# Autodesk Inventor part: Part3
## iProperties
Shininess: 64.0
Length Units: 11269
Angle Units: 11279
Time Units: 11290
Mass Units: 11283
Length Display Precision: 3
Angle Display Precision: 2
Compacted: True
Created: 2002-07
Part Number: Part3
Document SubType Name: Modeling
Designer: Administrator
Density: 0.0
Volumn: 0.0
Area: 0.0
PropertySet Name: Model Information
Control State: 0
Master: False
Checked Out: False
Author: Administrator
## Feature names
1. Extrusion1
2. Extrusion2
